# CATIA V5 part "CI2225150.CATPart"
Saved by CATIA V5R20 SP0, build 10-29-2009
Part number: CI2225150
Bounding box of the stored display mesh (mm): x -24 to 24, y -18.534 to 184.5, z -34.099 to 26.514
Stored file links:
  C:\Users\Raffaele\Desktop\3D X SITO CF\BOLEX\19-INCLINED ASSEMBLY REF_CI\CI2225150.CATPart
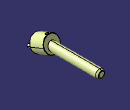
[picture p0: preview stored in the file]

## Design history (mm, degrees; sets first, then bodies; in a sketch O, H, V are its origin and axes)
Set1
  DatumSurface1 to DatumSurface16 "MANIFOLD_SOLID_BREP #393"
  DatumSurface17 to DatumSurface39 "MANIFOLD_SOLID_BREP #1138"
Body1 (main body)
